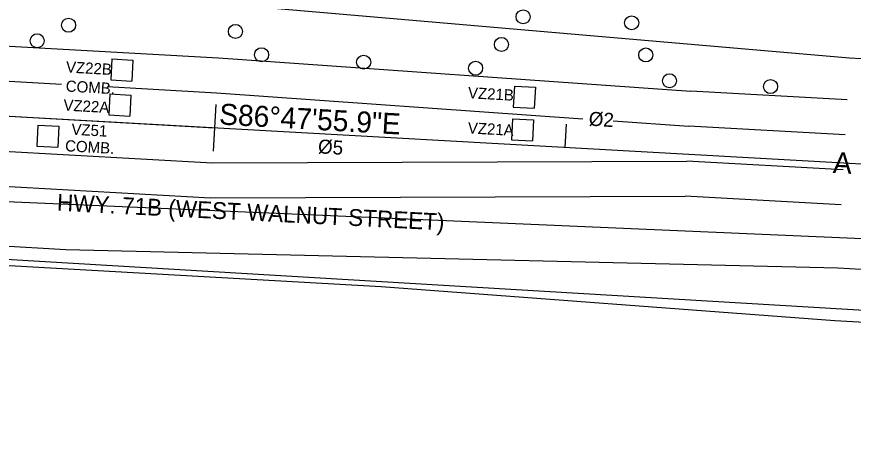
# Model space of a CAD drawing. Extents: x 679444 to 687671, y 733868 to 736107.
# Drawn here: x 683719.4 to 683957.9, y 734906.4 to 735025.5 of the extents above; entities that cross this region are included whole.
import ezdxf

# ---------------------------------------------------------------- set-up
doc = ezdxf.new("R2010")
doc.units = 0
for name, color, linetype in [('$', 7, 'Continuous'), ('Clipping Boundary', 7, 'Continuous'), ('MOT Stage 1', 7, 'Continuous'), ('MOT Stage 1 Lanes', 7, 'Continuous'), ('R_Horz Alg', 7, 'Continuous'), ('R_Horz Alg Station', 7, 'Continuous'), ('RW-EX', 7, 'Continuous'), ('RW-PR', 7, 'Continuous'), ('TITEXT', 7, 'Continuous'), ('Video-Zones-pr', 7, 'Continuous')]:
    doc.layers.add(name, color=color, linetype=linetype)

# ---------------------------------------------------------------- blocks, each defined once
blk = doc.blocks.new('BAREL_1617')
at = {"layer": 'MOT Stage 1'}
blk.add_circle((0, 0.01), 2.88, dxfattribs=at)
blk = doc.blocks.new('BAREL_1618')
at = {"layer": 'MOT Stage 1'}
blk.add_circle((0, 0.01), 2.88, dxfattribs=at)
blk = doc.blocks.new('BAREL_1682')
at = {"layer": 'MOT Stage 1'}
blk.add_circle((0, 0.01), 2.88, dxfattribs=at)
blk = doc.blocks.new('BAREL_1683')
at = {"layer": 'MOT Stage 1'}
blk.add_circle((0, 0.01), 2.88, dxfattribs=at)
blk = doc.blocks.new('BAREL_1684')
at = {"layer": 'MOT Stage 1'}
blk.add_circle((0, 0.01), 2.88, dxfattribs=at)
blk = doc.blocks.new('BAREL_1685')
at = {"layer": 'MOT Stage 1'}
blk.add_circle((0, 0.01), 2.88, dxfattribs=at)
blk = doc.blocks.new('BAREL_1686')
at = {"layer": 'MOT Stage 1'}
blk.add_circle((0, 0.01), 2.88, dxfattribs=at)
blk = doc.blocks.new('BAREL_1687')
at = {"layer": 'MOT Stage 1'}
blk.add_circle((0, 0.01), 2.88, dxfattribs=at)
blk = doc.blocks.new('BAREL_1688')
at = {"layer": 'MOT Stage 1'}
blk.add_circle((0, 0.01), 2.88, dxfattribs=at)
blk = doc.blocks.new('BAREL_1689')
at = {"layer": 'MOT Stage 1'}
blk.add_circle((0, 0.01), 2.88, dxfattribs=at)
blk = doc.blocks.new('BAREL_1690')
at = {"layer": 'MOT Stage 1'}
blk.add_circle((0, 0.01), 2.88, dxfattribs=at)
blk = doc.blocks.new('BAREL_1693')
at = {"layer": 'MOT Stage 1'}
blk.add_circle((0, 0.01), 2.88, dxfattribs=at)

msp = doc.modelspace()

# ---------------------------------------------------------------- linework, layer by layer
at = {"layer": 'Clipping Boundary'}
msp.add_lwpolyline([(683681.22, 734974.2), (683679.4, 734958.5), (684555.95, 734906.39), (684558.45, 734936.24)], close=True, dxfattribs=at)
at = {"layer": 'MOT Stage 1 Lanes'}
for p, q in [((683668.77, 735019.83), (683776.9, 735013.79)), ((683776.9, 735013.79), (683911.57, 735004.25)), ((683668.22, 735009.85), (683732.17, 735006.27)), ((683745.17, 735005.55), (683776.34, 735003.8)), ((683776.34, 735003.8), (683880.75, 734996.41)), ((683956.14, 735001.76), (683911.57, 735004.25)), ((683666.66, 734999.92), (683775.78, 734993.82)), ((683889.45, 734995.79), (683911.02, 734994.27)), ((683955.58, 734991.78), (683911.02, 734994.27)), ((683666.1, 734989.94), (683775.22, 734983.83)), ((683775.22, 734983.83), (683910.46, 734984.28)), ((683955.02, 734981.79), (683910.46, 734984.28)), ((683666.54, 734979.9), (683774.66, 734973.85)), ((683774.66, 734973.85), (683909.9, 734974.3)), ((683954.46, 734971.81), (683909.9, 734974.3))]:
    msp.add_line(p, q, dxfattribs=at)
at = {"layer": 'R_Horz Alg Station'}
for p, q in [((683602.68, 735003.5), (683955.13, 734983.79)), ((683955.13, 734983.79), (684762.18, 734938.65))]:
    msp.add_line(p, q, dxfattribs=at)
for points in [[(683776.15, 735000.48), (683775.41, 734987.16)], [(683876, 734994.89), (683875.62, 734988.23)]]:
    msp.add_lwpolyline(points, dxfattribs=at)
at = {"layer": 'RW-EX'}
for p, q in [((683737.17, 735032.78), (683956.81, 735013.74)), ((683956.81, 735013.74), (684210.56, 734999.55)), ((683657.53, 734963.37), (683733.41, 734959.13)), ((683733.41, 734959.13), (683953.46, 734953.83)), ((683953.46, 734953.83), (684015.02, 734950.39))]:
    msp.add_line(p, q, dxfattribs=at)
at = {"layer": 'RW-PR'}
msp.add_lwpolyline([(683648.18, 734950.88), (683683.55, 734956.41), (683823.33, 734948.59), (683952.62, 734938.86), (684206.41, 734924.66)], dxfattribs=at)
at = {"layer": 'Video-Zones-pr'}
for points in [[(683746.54, 735013.48), (683746.21, 735007.49)], [(683746.54, 735013.48), (683752.53, 735013.15)], [(683752.53, 735013.15), (683752.2, 735007.16)], [(683746.21, 735007.49), (683752.2, 735007.16)], [(683861.29, 735005.72), (683860.95, 734999.73)], [(683861.29, 735005.72), (683867.28, 735005.38)], [(683867.28, 735005.38), (683866.94, 734999.39)], [(683745.98, 735003.5), (683745.65, 734997.51)], [(683745.98, 735003.5), (683751.97, 735003.16)], [(683751.97, 735003.16), (683751.64, 734997.17)], [(683860.95, 734999.73), (683866.94, 734999.39)], [(683745.65, 734997.51), (683751.64, 734997.17)], [(683860.77, 734996.41), (683860.43, 734990.41)], [(683860.77, 734996.41), (683866.76, 734996.07)], [(683866.76, 734996.07), (683866.42, 734990.08)], [(683725.44, 734994.6), (683725.13, 734988.61)], [(683725.44, 734994.6), (683731.43, 734994.3)], [(683731.43, 734994.3), (683731.12, 734988.3)], [(683860.43, 734990.41), (683866.42, 734990.08)], [(683725.13, 734988.61), (683731.12, 734988.3)]]:
    msp.add_lwpolyline(points, dxfattribs=at)

# ---------------------------------------------------------------- block references
at = {"layer": 'MOT Stage 1', "xscale": 0.6945420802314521, "yscale": 0.6945420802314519}
for name, p, rotation in [('BAREL_1617', (683863.75, 735025.46), 87.04179557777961), ('BAREL_1618', (683894.7, 735023.75), 87.04179557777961), ('BAREL_1683', (683734.2, 735023.07), 87.04179557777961), ('BAREL_1685', (683781.75, 735021.31), 87.04179557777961), ('BAREL_1684', (683725.24, 735018.64), 87.04179557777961), ('BAREL_1687', (683857.59, 735017.59), 87.04179557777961), ('BAREL_1686', (683789.21, 735014.66), 87.04179557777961), ('BAREL_1689', (683898.72, 735014.59), 87.04179557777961), ('BAREL_1682', (683818.31, 735012.53), 122.09475922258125), ('BAREL_1688', (683850.23, 735010.81), 87.04179557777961), ('BAREL_1690', (683905.48, 735007.23), 87.04179557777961), ('BAREL_1693', (683934.29, 735005.57), 87.04179557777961)]:
    msp.add_blockref(name, p, dxfattribs=dict(at, rotation=rotation))

# ---------------------------------------------------------------- texts
at = {"layer": '$'}
for s, height, rotation, p in [('VZ22B', 3.2, 356.7989, (683733.38, 735009.6)), ('COMB.', 3.2, 356.7989, (683733.32, 735004.16)), ('VZ21B', 3.2, 356.7989, (683847.97, 735002.25)), ('VZ22A', 3.2, 356.7989, (683732.65, 734998.75)), ('VZ51', 3.2, 356.7989, (683734.93, 734991.84)), ('VZ21A', 3.2, 356.7989, (683847.92, 734992.23)), ('COMB.', 3.2, 356.7989, (683733.14, 734987.13)), ('HWY. 71B (WEST WALNUT STREET)', 4.8, 357.0637, (683730.8, 734970.18))]:
    msp.add_text(s, height=height, rotation=rotation, dxfattribs=at).set_placement(p)
at = {"layer": 'R_Horz Alg'}
msp.add_text('A', height=6, rotation=356.7989, dxfattribs=at).set_placement((683951.97, 734980.96))
at = {"layer": 'R_Horz Alg Station'}
msp.add_text('S86%%d47\'55.9"E', height=6, rotation=356.7989, dxfattribs=at).set_placement((683777.01, 734994.77))
at = {"layer": 'TITEXT'}
for s, p in [('%%C2', (683882.37, 734994.46)), ('%%C5', (683805.2, 734986.56))]:
    msp.add_text(s, height=4, rotation=356.2723, dxfattribs=at).set_placement(p)

doc.saveas('drawing.dxf')
